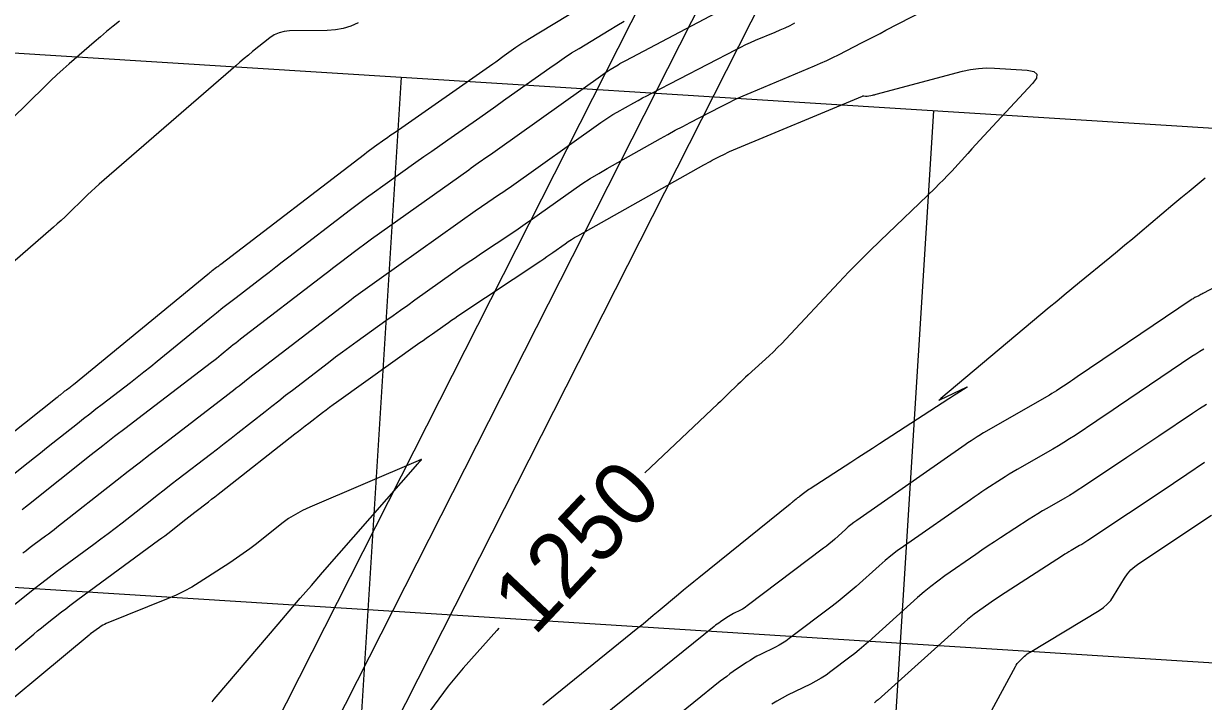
# Model space of a CAD drawing. Extents: x 658976 to 668721, y 639543 to 647196.
# Drawn here: x 662250.4 to 662361, y 642003 to 642066.5 of the extents above; entities that cross this region are included whole.
import ezdxf

# ---------------------------------------------------------------- set-up
doc = ezdxf.new("R2010")
doc.units = 0
for name, color, linetype in [('Ex_Contour Labels', 7, 'Continuous'), ('Ex_Major Contours', 7, 'Continuous'), ('Ex_Minor Contours', 7, 'Continuous'), ('R_Grid', 7, 'Continuous'), ('R_Water', 7, 'Continuous')]:
    doc.layers.add(name, color=color, linetype=linetype)

msp = doc.modelspace()

# ---------------------------------------------------------------- linework, layer by layer
at = {"layer": 'Ex_Major Contours'}
for points in [[(662238.32, 642019.41), (662253.53, 642031.47), (662253.61, 642031.53), (662253.68, 642031.59), (662253.75, 642031.64), (662253.82, 642031.7), (662254.11, 642031.93), (662254.18, 642031.99), (662254.25, 642032.05), (662254.33, 642032.1), (662254.4, 642032.16), (662254.73, 642032.41), (662254.81, 642032.47), (662254.89, 642032.53), (662254.97, 642032.6), (662255.05, 642032.66), (662267.66, 642043.01), (662267.76, 642043.09), (662267.86, 642043.17), (662267.96, 642043.25), (662268.06, 642043.33), (662268.46, 642043.64), (662268.57, 642043.72), (662268.67, 642043.79), (662268.77, 642043.87), (662268.87, 642043.95), (662282.33, 642054.26), (662282.57, 642054.44), (662282.8, 642054.61), (662283.04, 642054.79), (662283.28, 642054.96), (662284.24, 642055.64), (662284.48, 642055.81), (662284.72, 642055.98), (662284.96, 642056.15), (662285.2, 642056.32), (662294.36, 642062.72), (662294.64, 642062.91), (662294.91, 642063.1), (662295.18, 642063.3), (662295.45, 642063.49), (662296.54, 642064.26), (662296.82, 642064.46), (662297.1, 642064.64), (662297.38, 642064.82), (662297.66, 642065), (662306.29, 642070.24)], [(662281.74, 642066.56), (662281.05, 642066.25), (662280.34, 642066.03), (662279.61, 642065.9), (662278.85, 642065.84), (662275.3, 642065.8), (662274.8, 642065.75), (662274.33, 642065.63), (662273.88, 642065.43), (662273.46, 642065.14), (662271.85, 642063.86), (662271.45, 642063.54), (662271.05, 642063.21), (662270.66, 642062.88), (662270.27, 642062.54), (662257.46, 642051.43), (662257.09, 642051.1), (662256.73, 642050.77), (662256.37, 642050.44), (662256.02, 642050.1), (662254.61, 642048.72), (662254.26, 642048.38), (662253.9, 642048.04), (662253.53, 642047.71), (662253.16, 642047.39), (662239.7, 642035.73)], [(662244.39, 642003.51), (662250.95, 642008.95), (662251.32, 642009.25), (662251.69, 642009.56), (662252.06, 642009.86), (662252.44, 642010.15), (662253.94, 642011.34), (662254.32, 642011.63), (662254.7, 642011.93), (662255.08, 642012.21), (662255.46, 642012.5), (662263.03, 642018.05), (662263.32, 642018.27), (662263.6, 642018.48), (662263.89, 642018.7), (662264.17, 642018.92), (662265.31, 642019.81), (662265.59, 642020.04), (662265.87, 642020.26), (662266.16, 642020.48), (662266.44, 642020.7), (662267.7, 642021.66), (662268, 642021.9), (662268.31, 642022.13), (662268.61, 642022.37), (662268.91, 642022.61), (662275.82, 642028.04), (662276.15, 642028.29), (662276.47, 642028.54), (662276.79, 642028.79), (662277.11, 642029.04), (662278.41, 642030.03), (662278.73, 642030.28), (662279.06, 642030.52), (662279.39, 642030.77), (662279.72, 642031), (662287.54, 642036.58), (662287.84, 642036.79), (662288.13, 642037), (662288.43, 642037.21), (662288.72, 642037.42), (662289.91, 642038.26), (662290.2, 642038.47), (662290.5, 642038.68), (662290.8, 642038.88), (662291.1, 642039.08), (662298.86, 642044.25), (662299.15, 642044.44), (662299.44, 642044.64), (662299.73, 642044.84), (662300.01, 642045.04), (662301.16, 642045.85), (662301.44, 642046.05), (662301.74, 642046.24), (662302.04, 642046.43), (662302.34, 642046.6), (662314.15, 642053.24), (662314.35, 642053.35), (662314.55, 642053.46), (662314.75, 642053.57), (662314.95, 642053.67), (662315.76, 642054.09), (662315.96, 642054.19), (662316.16, 642054.29), (662316.37, 642054.39), (662316.58, 642054.48), (662329.03, 642059.69), (662329.06, 642059.71), (662329.1, 642059.71), (662329.13, 642059.72), (662329.17, 642059.71), (662329.32, 642059.69), (662329.36, 642059.69), (662329.4, 642059.68), (662329.43, 642059.69), (662329.47, 642059.69), (662329.96, 642059.78), (662330.06, 642059.8), (662330.15, 642059.82), (662330.24, 642059.84), (662330.33, 642059.86), (662338.42, 642062.02), (662339.16, 642062.19), (662339.91, 642062.29), (662340.67, 642062.33), (662341.43, 642062.31), (662344.49, 642062.11), (662345.1, 642061.99), (662345.38, 642061.75), (662345.34, 642061.37), (662344.98, 642060.88), (662340.43, 642055.96), (662340.05, 642055.55), (662339.67, 642055.14), (662339.29, 642054.73), (662338.91, 642054.31), (662337.4, 642052.66), (662337.02, 642052.26), (662336.63, 642051.85), (662336.24, 642051.46), (662335.84, 642051.07), (662330.68, 642046.12), (662329.7, 642045.16), (662328.72, 642044.19), (662327.76, 642043.21), (662326.81, 642042.21), (662321.85, 642036.91), (662321.46, 642036.51), (662321.08, 642036.12), (662320.68, 642035.73), (662320.27, 642035.35), (662318.31, 642033.55), (662318.07, 642033.33), (662317.83, 642033.1), (662317.6, 642032.88), (662317.36, 642032.65), (662316.42, 642031.74), (662316.19, 642031.52), (662315.95, 642031.29), (662315.72, 642031.07), (662315.48, 642030.84), (662308.64, 642024.38)], [(662361.1, 642025.33), (662359.45, 642024.22), (662359.03, 642023.94), (662358.62, 642023.66), (662358.21, 642023.39), (662357.79, 642023.11), (662350.18, 642018.04), (662349.98, 642017.91), (662349.79, 642017.79), (662349.59, 642017.67), (662349.39, 642017.55), (662348.59, 642017.09), (662348.39, 642016.98), (662348.19, 642016.86), (662348, 642016.74), (662347.8, 642016.61), (662342.41, 642013.13), (662342.08, 642012.91), (662341.76, 642012.69), (662341.43, 642012.47), (662341.11, 642012.25), (662339.82, 642011.35), (662339.5, 642011.12), (662339.19, 642010.88), (662338.88, 642010.63), (662338.59, 642010.37), (662330.5, 642003.11), (662330.33, 642002.96), (662330.17, 642002.82)], [(662294.93, 642009.82), (662294.74, 642009.61), (662291.59, 642006.07), (662291.11, 642005.51), (662290.64, 642004.95), (662290.18, 642004.37), (662289.74, 642003.79), (662287.99, 642001.42)]]:
    msp.add_lwpolyline(points, dxfattribs=at)
at = {"layer": 'Ex_Minor Contours'}
for points in [[(662248.08, 642010.92), (662251.42, 642013.55), (662252.09, 642014.08), (662252.77, 642014.6), (662253.46, 642015.12), (662254.15, 642015.63), (662256.95, 642017.69), (662257.62, 642018.18), (662258.29, 642018.68), (662258.95, 642019.19), (662259.61, 642019.7), (662262.23, 642021.76), (662262.89, 642022.28), (662263.54, 642022.79), (662264.2, 642023.3), (662264.86, 642023.81), (662267.89, 642026.14), (662268.54, 642026.64), (662269.18, 642027.13), (662269.82, 642027.63), (662270.46, 642028.13), (662273.01, 642030.14), (662273.65, 642030.64), (662274.29, 642031.14), (662274.94, 642031.64), (662275.58, 642032.13), (662278.96, 642034.73), (662279.63, 642035.24), (662280.29, 642035.73), (662280.97, 642036.23), (662281.64, 642036.71), (662284.35, 642038.65), (662285.03, 642039.13), (662285.71, 642039.61), (662286.39, 642040.1), (662287.07, 642040.58), (662290.62, 642043.11), (662291.29, 642043.58), (662291.96, 642044.05), (662292.64, 642044.51), (662293.32, 642044.97), (662296.05, 642046.78), (662296.74, 642047.24), (662297.41, 642047.7), (662298.09, 642048.17), (662298.76, 642048.64), (662301.97, 642050.92), (662302.73, 642051.45), (662303.51, 642051.96), (662304.3, 642052.44), (662305.1, 642052.91), (662310.09, 642055.71), (662310.78, 642056.1), (662311.48, 642056.48), (662312.18, 642056.85), (662312.89, 642057.22), (662315.71, 642058.68), (662316.42, 642059.04), (662317.13, 642059.39), (662317.86, 642059.71), (662318.59, 642060.03), (662324.54, 642062.52), (662325.11, 642062.77), (662325.68, 642063.03), (662326.24, 642063.3), (662326.79, 642063.57), (662329.01, 642064.71), (662329.57, 642065), (662330.12, 642065.29), (662330.68, 642065.57), (662331.23, 642065.86), (662337.14, 642068.94)], [(662250.24, 642020.94), (662250.54, 642021.18), (662250.84, 642021.42), (662256.72, 642026.09), (662257.8, 642026.95), (662258.89, 642027.8), (662259.98, 642028.64), (662261.07, 642029.48), (662267.99, 642034.74), (662268.22, 642034.92), (662268.45, 642035.1), (662268.68, 642035.28), (662268.9, 642035.47), (662269.8, 642036.21), (662270.03, 642036.39), (662270.26, 642036.57), (662270.49, 642036.75), (662270.72, 642036.93), (662278.63, 642043), (662278.99, 642043.27), (662279.35, 642043.55), (662279.71, 642043.83), (662280.08, 642044.11), (662281.53, 642045.22), (662281.89, 642045.49), (662282.25, 642045.76), (662282.62, 642046.03), (662282.99, 642046.3), (662292.11, 642052.79), (662292.34, 642052.95), (662292.56, 642053.11), (662292.79, 642053.27), (662293.01, 642053.43), (662293.91, 642054.06), (662294.14, 642054.21), (662294.36, 642054.37), (662294.59, 642054.53), (662294.81, 642054.69), (662304.68, 642061.71), (662304.85, 642061.84), (662305.02, 642061.95), (662305.2, 642062.07), (662305.38, 642062.18), (662306.11, 642062.62), (662306.29, 642062.73), (662306.47, 642062.83), (662306.65, 642062.93), (662306.84, 642063.03), (662317.57, 642068.67)], [(662244.13, 642020.06), (662250.81, 642025.35), (662251.38, 642025.81), (662251.96, 642026.26), (662252.53, 642026.72), (662253.11, 642027.18), (662255.41, 642029.01), (662255.99, 642029.47), (662256.57, 642029.92), (662257.15, 642030.37), (662257.74, 642030.82), (662260.4, 642032.84), (662261.03, 642033.33), (662261.66, 642033.83), (662262.29, 642034.33), (662262.91, 642034.83), (662267.85, 642038.88), (662268.45, 642039.38), (662269.06, 642039.86), (662269.68, 642040.35), (662270.29, 642040.82), (662272.77, 642042.72), (662273.39, 642043.2), (662274.01, 642043.67), (662274.63, 642044.15), (662275.25, 642044.62), (662281.03, 642049.05), (662281.78, 642049.62), (662282.53, 642050.18), (662283.29, 642050.73), (662284.05, 642051.28), (662287.15, 642053.49), (662287.9, 642054.02), (662288.64, 642054.54), (662289.39, 642055.07), (662290.14, 642055.59), (662293.14, 642057.69), (662293.89, 642058.21), (662294.64, 642058.74), (662295.38, 642059.27), (662296.13, 642059.8), (662299.71, 642062.35), (662300.39, 642062.82), (662301.07, 642063.28), (662301.76, 642063.73), (662302.46, 642064.16), (662305.28, 642065.87), (662305.99, 642066.29), (662306.7, 642066.71)], [(662259.36, 642066.71), (662258.76, 642066.23), (662258.16, 642065.73), (662257.57, 642065.24), (662256.99, 642064.73), (662254.65, 642062.71), (662254.07, 642062.2), (662253.5, 642061.68), (662252.94, 642061.15), (662252.38, 642060.62), (662244.46, 642052.87)], [(662250.31, 642016.88), (662250.57, 642017.08), (662250.84, 642017.29), (662251.1, 642017.49), (662251.37, 642017.68), (662252.44, 642018.47), (662252.71, 642018.67), (662252.98, 642018.87), (662253.24, 642019.07), (662253.5, 642019.28), (662259.15, 642023.71), (662260.18, 642024.52), (662261.21, 642025.32), (662262.25, 642026.12), (662263.28, 642026.92), (662269.53, 642031.73), (662269.79, 642031.93), (662270.05, 642032.13), (662270.31, 642032.33), (662270.57, 642032.53), (662271.6, 642033.34), (662271.86, 642033.55), (662272.12, 642033.75), (662272.38, 642033.95), (662272.64, 642034.15), (662281.08, 642040.63), (662281.3, 642040.8), (662281.52, 642040.96), (662281.74, 642041.12), (662281.96, 642041.28), (662282.84, 642041.91), (662283.06, 642042.07), (662283.28, 642042.22), (662283.5, 642042.38), (662283.72, 642042.54), (662292.93, 642049.09), (662293.17, 642049.26), (662293.42, 642049.43), (662293.67, 642049.6), (662293.91, 642049.76), (662294.9, 642050.42), (662295.15, 642050.59), (662295.4, 642050.75), (662295.64, 642050.92), (662295.89, 642051.1), (662304.5, 642057.21), (662304.87, 642057.47), (662305.25, 642057.72), (662305.64, 642057.95), (662306.03, 642058.18), (662307.61, 642059.07), (662308.01, 642059.29), (662308.4, 642059.51), (662308.8, 642059.72), (662309.21, 642059.93), (662317.19, 642064.07), (662317.64, 642064.29), (662318.09, 642064.51), (662318.55, 642064.72), (662319.01, 642064.92), (662320.86, 642065.69), (662321.33, 642065.89), (662321.78, 642066.1), (662322.24, 642066.32), (662322.69, 642066.54)], [(662361.16, 642052.01), (662360.41, 642051.38), (662359.66, 642050.75), (662358.9, 642050.12), (662358.15, 642049.49), (662355.05, 642046.88), (662354.35, 642046.29), (662353.65, 642045.7), (662352.94, 642045.11), (662352.23, 642044.53), (662349.38, 642042.21), (662348.67, 642041.63), (662347.96, 642041.04), (662347.26, 642040.45), (662346.55, 642039.87), (662336.38, 642031.34), (662336.37, 642031.33), (662336.35, 642031.31), (662336.32, 642031.29), (662336.31, 642031.27), (662336.29, 642031.26), (662336.22, 642031.2), (662336.21, 642031.19), (662336.21, 642031.19), (662336.21, 642031.19), (662336.22, 642031.19), (662336.29, 642031.23), (662336.31, 642031.24), (662336.32, 642031.25), (662336.34, 642031.25), (662336.36, 642031.26), (662338.79, 642032.41), (662338.8, 642032.41), (662338.8, 642032.41), (662338.81, 642032.41), (662338.82, 642032.42), (662338.85, 642032.43), (662338.86, 642032.43), (662338.86, 642032.43), (662338.86, 642032.43), (662338.86, 642032.42), (662337.82, 642031.76), (662337.65, 642031.65), (662337.47, 642031.54), (662337.3, 642031.42), (662337.12, 642031.31), (662330.64, 642027.09), (662329.97, 642026.65), (662329.29, 642026.21), (662328.61, 642025.77), (662327.94, 642025.34), (662324.12, 642022.88), (662324, 642022.8), (662323.88, 642022.72), (662323.76, 642022.63), (662323.64, 642022.54), (662323.1, 642022.13), (662323.03, 642022.07), (662322.95, 642022.02), (662322.88, 642021.96), (662322.81, 642021.9), (662322.52, 642021.67), (662322.45, 642021.61), (662322.38, 642021.55), (662322.31, 642021.49), (662322.24, 642021.43), (662313.69, 642014.54), (662313.21, 642014.15), (662312.73, 642013.76), (662312.26, 642013.37), (662311.78, 642012.97), (662309.89, 642011.38), (662309.41, 642010.99), (662308.93, 642010.59), (662308.46, 642010.2), (662307.98, 642009.81), (662299.05, 642002.61)], [(662373.66, 642047.87), (662360.96, 642041.17), (662360.86, 642041.12), (662360.77, 642041.08), (662360.68, 642041.03), (662360.58, 642040.98), (662360.21, 642040.8), (662360.12, 642040.75), (662360.03, 642040.7), (662359.94, 642040.65), (662359.85, 642040.59), (662349.17, 642033.36), (662348.96, 642033.22), (662348.74, 642033.07), (662348.53, 642032.93), (662348.31, 642032.78), (662347.45, 642032.21), (662347.23, 642032.07), (662347.01, 642031.93), (662346.79, 642031.8), (662346.57, 642031.66), (662340.39, 642028.11), (662340.24, 642028.03), (662340.09, 642027.94), (662339.94, 642027.85), (662339.8, 642027.75), (662339.22, 642027.38), (662339.08, 642027.28), (662338.93, 642027.19), (662338.79, 642027.09), (662338.65, 642026.99), (662328.5, 642019.91), (662328.22, 642019.72), (662327.95, 642019.51), (662327.69, 642019.3), (662327.44, 642019.07), (662326.43, 642018.17), (662326.18, 642017.95), (662325.92, 642017.73), (662325.65, 642017.51), (662325.39, 642017.31), (662318.23, 642011.9), (662318.08, 642011.79), (662317.93, 642011.69), (662317.77, 642011.6), (662317.61, 642011.51), (662316.94, 642011.18), (662316.78, 642011.1), (662316.62, 642011.01), (662316.46, 642010.91), (662316.31, 642010.82), (662315.71, 642010.41), (662315.56, 642010.3), (662315.41, 642010.2), (662315.26, 642010.09), (662315.12, 642009.97), (662303.67, 642000.73)], [(662361.06, 642035.96), (662360.67, 642035.74), (662360.29, 642035.51), (662359.92, 642035.27), (662353.05, 642030.62), (662352.55, 642030.28), (662352.04, 642029.94), (662351.52, 642029.59), (662351.01, 642029.25), (662348.97, 642027.89), (662348.45, 642027.55), (662347.93, 642027.23), (662347.41, 642026.91), (662346.88, 642026.6), (662343.54, 642024.68), (662343.17, 642024.46), (662342.79, 642024.24), (662342.42, 642024.01), (662342.06, 642023.78), (662340.6, 642022.83), (662340.24, 642022.59), (662339.88, 642022.35), (662339.52, 642022.11), (662339.16, 642021.86), (662332.88, 642017.48), (662332.29, 642017.06), (662331.71, 642016.61), (662331.15, 642016.15), (662330.6, 642015.67), (662328.43, 642013.72), (662327.88, 642013.24), (662327.32, 642012.77), (662326.76, 642012.32), (662326.18, 642011.87), (662322.17, 642008.84), (662321.86, 642008.61), (662321.54, 642008.4), (662321.21, 642008.21), (662320.87, 642008.03), (662319.48, 642007.35), (662319.14, 642007.18), (662318.81, 642006.99), (662318.49, 642006.8), (662318.17, 642006.59), (662316.92, 642005.74), (662316.61, 642005.52), (662316.3, 642005.3), (662316, 642005.07), (662315.7, 642004.84), (662308.29, 641998.85)], [(662361.31, 642030.78), (662360.64, 642030.38), (662359.99, 642029.95), (662356.82, 642027.81), (662356.07, 642027.3), (662355.33, 642026.8), (662354.58, 642026.3), (662353.83, 642025.8), (662349.68, 642023.04), (662349.27, 642022.77), (662348.86, 642022.51), (662348.44, 642022.26), (662348.02, 642022.01), (662346.33, 642021.04), (662345.91, 642020.8), (662345.49, 642020.54), (662345.08, 642020.29), (662344.67, 642020.03), (662341.98, 642018.29), (662341.4, 642017.9), (662340.82, 642017.52), (662340.24, 642017.13), (662339.67, 642016.73), (662336.77, 642014.71), (662336.11, 642014.23), (662335.46, 642013.73), (662334.83, 642013.22), (662334.21, 642012.68), (662329.59, 642008.53), (662329.17, 642008.16), (662328.74, 642007.8), (662328.31, 642007.45), (662327.86, 642007.11), (662326.07, 642005.75), (662325.62, 642005.42), (662325.15, 642005.12), (662324.67, 642004.84), (662324.17, 642004.58), (662322.02, 642003.52), (662321.51, 642003.26), (662321.01, 642002.97), (662320.52, 642002.68)], [(662268.05, 642002.91), (662268.24, 642003.15), (662268.44, 642003.38), (662274.25, 642010.2), (662275.28, 642011.41), (662276.32, 642012.62), (662277.36, 642013.82), (662278.41, 642015.02), (662287.33, 642025.21), (662287.35, 642025.23), (662287.37, 642025.26), (662287.39, 642025.28), (662287.41, 642025.3), (662287.52, 642025.44), (662287.53, 642025.45), (662287.54, 642025.46), (662287.57, 642025.49), (662287.58, 642025.5), (662287.58, 642025.5), (662287.68, 642025.6), (662287.69, 642025.61), (662287.69, 642025.62), (662287.68, 642025.62), (662287.66, 642025.62), (662287.55, 642025.57), (662287.54, 642025.56), (662287.52, 642025.56), (662287.51, 642025.55), (662287.49, 642025.54), (662287.43, 642025.52), (662287.42, 642025.51), (662287.4, 642025.5), (662287.39, 642025.5), (662287.37, 642025.49), (662277.22, 642021.17), (662276.53, 642020.85), (662275.86, 642020.48), (662275.22, 642020.08), (662274.6, 642019.62), (662272.2, 642017.73), (662271.59, 642017.26), (662270.97, 642016.81), (662270.35, 642016.37), (662269.71, 642015.95), (662266.85, 642014.1), (662266.15, 642013.67), (662265.43, 642013.27), (662264.69, 642012.91), (662263.94, 642012.59), (662258.11, 642010.24), (662257.95, 642010.17), (662257.79, 642010.09), (662257.64, 642009.99), (662257.49, 642009.89), (662256.64, 642009.27), (662256.63, 642009.26), (662256.62, 642009.25), (662256.61, 642009.24), (662256.6, 642009.24), (662256.56, 642009.21), (662256.54, 642009.19), (662256.52, 642009.17), (662244.83, 641999.48)], [(662338.54, 641997.28), (662343.38, 642006.22), (662343.46, 642006.36), (662343.55, 642006.49), (662343.66, 642006.62), (662343.77, 642006.73), (662344.24, 642007.19), (662344.36, 642007.3), (662344.49, 642007.4), (662344.62, 642007.49), (662344.76, 642007.58), (662351.22, 642011.47), (662351.63, 642011.75), (662351.99, 642012.06), (662352.31, 642012.42), (662352.59, 642012.82), (662353.62, 642014.51), (662353.9, 642014.91), (662354.21, 642015.27), (662354.57, 642015.6), (662354.96, 642015.89), (662361.76, 642020.42)]]:
    msp.add_lwpolyline(points, dxfattribs=at)
at = {"layer": 'R_Grid'}
for p, q in [((661637.1, 642102.2), (663134.15, 642008.18)), ((662270.15, 641811.95), (662285.82, 642061.45)), ((662320.05, 641808.81), (662335.72, 642058.32)), ((661633.97, 642052.3), (663131.02, 641958.27))]:
    msp.add_line(p, q, dxfattribs=at)
at = {"layer": 'R_Water'}
for p, q in [((662216.73, 641887.88), (662333.31, 642117.78)), ((662221.19, 641885.62), (662337.77, 642115.51)), ((662225.65, 641883.36), (662342.23, 642113.25))]:
    msp.add_line(p, q, dxfattribs=at)

# ---------------------------------------------------------------- texts
at = {"layer": 'Ex_Contour Labels'}
msp.add_text('1250', height=6, rotation=46.7155, dxfattribs=at).set_placement((662298.25, 642008.98))

doc.saveas('drawing.dxf')
